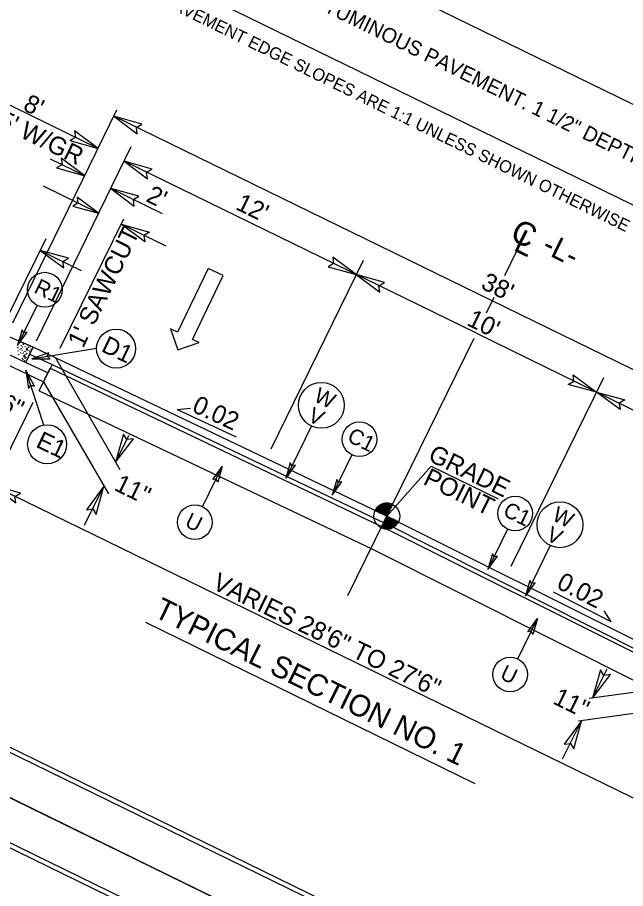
# Model space of a CAD drawing. Extents: x 1518247 to 1523638, y 635234 to 639927.
# Drawn here: x 1521566.4 to 1521902.2, y 638576.7 to 639057.9 of the extents above; entities that cross this region are included whole.
import ezdxf

# ---------------------------------------------------------------- set-up
doc = ezdxf.new("R2010")
doc.units = 0
for name, color, linetype in [('Default', 7, 'Continuous'), ('DTM TIN Hull White', 7, 'Continuous'), ('Old_Level_21', 7, 'Continuous'), ('Prop Dimension', 7, 'Continuous'), ('Prop Dimension Text', 7, 'Continuous'), ('Prop Lane Arrow CELL', 7, 'Continuous'), ('Prop Shade Light', 7, 'Continuous'), ('Sheet Cutting Line CELL', 7, 'Continuous'), ('Sheet Plot Border Inside CELL', 7, 'Continuous'), ('Sheet Plot Border Outside CELL', 7, 'Continuous'), ('Sheet Typical CELL', 7, 'Continuous'), ('Typical Curb CELL', 7, 'Continuous'), ('Typical Grade Point Symbol CELL', 7, 'Continuous'), ('Typical ID Circle CELL', 7, 'Continuous'), ('Typical Pavement Slope CELL', 7, 'Continuous'), ('Typical Pavement Slope Information CELL', 7, 'Continuous'), ('Typical Text Centerline CELL', 7, 'Continuous'), ('Typical Text Grade Point CELL', 7, 'Continuous'), ('Typical Text ID Circle CELL', 7, 'Continuous'), ('Typical Text Label CELL', 7, 'Continuous')]:
    doc.layers.add(name, color=color, linetype=linetype)

# ---------------------------------------------------------------- blocks, each defined once
blk = doc.blocks.new('TERMINATOR')
at = {"layer": 'Prop Shade Light'}
blk.add_lwpolyline([(-0.469, 0.081), (0, 0), (-0.471, -0.083), (-0.411, 0)], close=True, dxfattribs=at)

msp = doc.modelspace()

# ---------------------------------------------------------------- linework, layer by layer
at = {"layer": 'Default'}
for points in [[(1522438.02, 638198.63), (1520925.25, 638938.49), (1521408.53, 639926.64), (1522921.3, 639186.78)], [(1520441.97, 637950.34), (1521954.73, 637210.48), (1522438.02, 638198.63), (1520925.25, 638938.49)]]:
    msp.add_lwpolyline(points, close=True, dxfattribs=at)
at = {"layer": 'DTM TIN Hull White'}
for p, q in [((1521578.45, 638851.68), (1521584.56, 638864.18)), ((1521584.56, 638864.18), (1521767.55, 638776.75)), ((1521578.45, 638851.68), (1521762.16, 638764.31)), ((1521949.57, 638685.65), (1521767.55, 638776.75)), ((1521943.46, 638673.16), (1521761.27, 638764.74))]:
    msp.add_line(p, q, dxfattribs=at)
at = {"layer": 'Prop Dimension'}
for p, q in [((1521610.99, 638985.59), (1521539.35, 639020.56)), ((1521563.96, 638889.26), (1521621.37, 639006.86)), ((1522037.58, 638799.28), (1521619.64, 639003.32)), ((1521576.87, 638879.35), (1521629.21, 638986.56)), ((1521603.63, 638970.46), (1521584.63, 638979.74)), ((1521819.91, 638883.5), (1521625.28, 638978.51)), ((1521611.26, 638949.8), (1521580.79, 638964.67)), ((1521646.5, 638949.53), (1521617.96, 638963.47)), ((1521589.97, 638875.29), (1521625.26, 638946.72)), ((1521648.52, 638931.58), (1521623.76, 638943.67)), ((1521560.46, 638891.25), (1521582.21, 638935.81)), ((1521579.02, 638929.27), (1521601.58, 638918.22)), ((1521706.53, 638819.6), (1521757.45, 638923.89)), ((1521819.91, 638883.5), (1522014.4, 638788.21)), ((1521587.36, 638869.93), (1521622.98, 638808.23)), ((1521839.12, 638754.75), (1521890.18, 638858.97)), ((1521580.88, 638856.62), (1521616.63, 638794.7)), ((1521549.01, 638792.36), (1521575.18, 638845.34)), ((1521620.66, 638812.25), (1521628.06, 638827.23)), ((1521794.86, 638810.04), (1521770.4, 638782.47)), ((1521918.24, 638620.97), (1521552.58, 638799.48)), ((1521603.45, 638777.4), (1521614.13, 638799.03)), ((1521884.07, 638681.96), (1521892.01, 638698.04)), ((1521952.32, 638691.4), (1521882.21, 638681.7)), ((1521946.26, 638678.93), (1521876.19, 638669.24)), ((1521867.46, 638648.34), (1521877.9, 638669.47))]:
    msp.add_line(p, q, dxfattribs=at)
at = {"layer": 'Prop Lane Arrow CELL'}
for p, q in [((1521671.77, 638919.3), (1521654.8, 638884.11)), ((1521680.07, 638915.3), (1521671.77, 638919.3)), ((1521663.09, 638880.11), (1521680.07, 638915.3)), ((1521654.8, 638884.11), (1521651.02, 638885.93)), ((1521651.02, 638885.93), (1521655, 638874.25)), ((1521655, 638874.25), (1521666.86, 638878.29)), ((1521666.86, 638878.29), (1521663.09, 638880.11))]:
    msp.add_line(p, q, dxfattribs=at)
at = {"layer": 'Prop Shade Light'}
for points in [[(1521568.97, 638885.32), (1521566.45, 638876.67), (1521571.78, 638884), (1521569.87, 638883.68)], [(1521583.84, 638872.72), (1521574.29, 638869.34), (1521584.48, 638869.28), (1521582.92, 638870.82)], [(1521575.86, 638854.19), (1521571.05, 638863.11), (1521572.57, 638853.02), (1521573.84, 638854.8)], [(1521674.27, 638802.64), (1521679.55, 638809.94), (1521677.04, 638801.23), (1521676.12, 638802.94)], [(1521717.1, 638811.92), (1521714.58, 638803.28), (1521719.92, 638810.6), (1521718, 638810.28)], [(1521742.73, 638802.74), (1521740.21, 638794.09), (1521745.54, 638801.42), (1521743.62, 638801.1)], [(1521828.73, 638761.71), (1521826.21, 638753.06), (1521831.55, 638760.39), (1521829.63, 638760.06)], [(1521849.42, 638746.92), (1521846.9, 638738.27), (1521852.23, 638745.6), (1521850.32, 638745.27)], [(1521848.32, 638718.56), (1521853.6, 638725.86), (1521851.08, 638717.15), (1521850.17, 638718.86)]]:
    msp.add_lwpolyline(points, close=True, dxfattribs=at)
at = {"layer": 'Sheet Cutting Line CELL'}
for p, q in [((1520925.25, 638938.49), (1522438.02, 638198.63)), ((1522438.02, 638198.63), (1520925.25, 638938.49))]:
    msp.add_line(p, q, dxfattribs=at)
at = {"layer": 'Sheet Plot Border Inside CELL'}
for points in [[(1522907.39, 639168.59), (1521410.35, 639900.76), (1520946.79, 638952.95), (1522443.84, 638220.77)], [(1522424.11, 638180.44), (1520927.06, 638912.61), (1520463.51, 637964.8), (1521960.55, 637232.62)]]:
    msp.add_lwpolyline(points, close=True, dxfattribs=at)
at = {"layer": 'Sheet Plot Border Outside CELL'}
for points in [[(1522921.3, 639186.78), (1521408.53, 639926.64), (1520925.25, 638938.49), (1522438.02, 638198.63)], [(1522438.02, 638198.63), (1520925.25, 638938.49), (1520441.97, 637950.34), (1521954.73, 637210.48)]]:
    msp.add_lwpolyline(points, close=True, dxfattribs=at)
at = {"layer": 'Sheet Typical CELL'}
for p, q in [((1521639.08, 639140.63), (1522147.89, 638891.78)), ((1521617.12, 639095.71), (1522125.92, 638846.87))]:
    msp.add_line(p, q, dxfattribs=at)
for points in [[(1522895.04, 639171.79), (1521547.57, 639830.81), (1521086.25, 638887.58), (1522433.73, 638228.56)], [(1522411.76, 638183.64), (1521064.29, 638842.66), (1520602.97, 637899.43), (1521950.45, 637240.41)]]:
    msp.add_lwpolyline(points, close=True, dxfattribs=at)
at = {"layer": 'Typical Curb CELL'}
for p, q in [((1521575.12, 638875.77), (1521562.32, 638881.37)), ((1521552.95, 638875.79), (1521571.04, 638867.41)), ((1521571.04, 638867.41), (1521575.12, 638875.77)), ((1521571.85, 638875.38), (1521571.21, 638874.68)), ((1521571.21, 638874.68), (1521572.05, 638874.22)), ((1521572.05, 638874.22), (1521571.85, 638875.38)), ((1521570.42, 638871.5), (1521569.77, 638870.81)), ((1521569.77, 638870.81), (1521570.62, 638870.34)), ((1521570.62, 638870.34), (1521570.42, 638871.5))]:
    msp.add_line(p, q, dxfattribs=at)
for centre in [(1521566.8, 638878.51), (1521567.83, 638878.45), (1521569.72, 638877.34), (1521569.77, 638877.76), (1521566.68, 638875.47), (1521566.86, 638873.66), (1521567.73, 638874.41), (1521568.19, 638872.66), (1521568.52, 638876.65), (1521568.54, 638875.02), (1521569.06, 638874.01), (1521569.25, 638872.23), (1521569.32, 638876.01), (1521569.81, 638872.86), (1521570.61, 638873.46), (1521570.69, 638876.1), (1521571.25, 638876.73), (1521571.52, 638872.41), (1521572.5, 638875.77), (1521572.53, 638876.66), (1521572.7, 638873.9), (1521573.23, 638873.24), (1521573.5, 638876.04), (1521573.84, 638874.77), (1521574.14, 638874.06), (1521574.36, 638874.82), (1521567.06, 638871.79), (1521569.18, 638869.58), (1521569.62, 638868.92), (1521570.42, 638868.28), (1521570.81, 638869.61), (1521571.07, 638871.9), (1521571.27, 638870.03), (1521572.4, 638870.89), (1521573.1, 638871.83)]:
    msp.add_circle(centre, 0.064, dxfattribs=at)
at = {"layer": 'Typical Grade Point Symbol CELL'}
for p, q in [((1521764, 638785.62), (1521770.4, 638782.47)), ((1521770.4, 638782.47), (1521764, 638785.62)), ((1521773.54, 638788.88), (1521770.4, 638782.47)), ((1521767.26, 638776.06), (1521770.4, 638782.47)), ((1521770.4, 638782.47), (1521776.81, 638779.33))]:
    msp.add_line(p, q, dxfattribs=at)
for points in [[(1521770.45, 638782.57), (1521764.04, 638785.71), (1521764.04, 638785.71)], [(1521770.51, 638782.7), (1521764.1, 638785.84)], [(1521770.58, 638782.82), (1521764.18, 638785.96)], [(1521770.64, 638782.95), (1521764.24, 638786.09)], [(1521770.7, 638783.08), (1521764.32, 638786.21)], [(1521770.77, 638783.21), (1521764.4, 638786.33)], [(1521770.83, 638783.34), (1521764.48, 638786.45)], [(1521770.89, 638783.47), (1521764.57, 638786.56)], [(1521770.95, 638783.59), (1521764.64, 638786.69)], [(1521771.02, 638783.72), (1521764.73, 638786.8)], [(1521771.08, 638783.85), (1521764.83, 638786.91)], [(1521771.14, 638783.98), (1521764.92, 638787.03)], [(1521771.21, 638784.11), (1521765.01, 638787.14)], [(1521771.27, 638784.23), (1521765.11, 638787.25)], [(1521771.33, 638784.36), (1521765.21, 638787.36)], [(1521771.39, 638784.49), (1521765.31, 638787.47)], [(1521771.46, 638784.62), (1521765.42, 638787.58)], [(1521771.52, 638784.75), (1521765.52, 638787.69)], [(1521771.58, 638784.88), (1521765.64, 638787.79)], [(1521771.65, 638785), (1521765.76, 638787.89)], [(1521771.71, 638785.13), (1521765.88, 638787.99)], [(1521771.77, 638785.26), (1521766, 638788.09)], [(1521771.83, 638785.39), (1521766.12, 638788.19)], [(1521771.9, 638785.52), (1521766.26, 638788.28)], [(1521771.96, 638785.64), (1521766.39, 638788.37)], [(1521772.02, 638785.77), (1521766.52, 638788.47)], [(1521772.09, 638785.9), (1521766.67, 638788.55)], [(1521772.15, 638786.03), (1521766.82, 638788.64)], [(1521772.21, 638786.16), (1521766.97, 638788.73)], [(1521772.27, 638786.29), (1521767.12, 638788.81)], [(1521772.34, 638786.41), (1521767.28, 638788.89)], [(1521772.4, 638786.54), (1521767.44, 638788.97)], [(1521772.46, 638786.67), (1521767.62, 638789.04)], [(1521772.53, 638786.8), (1521767.8, 638789.12)], [(1521772.59, 638786.93), (1521767.97, 638789.19)], [(1521772.65, 638787.05), (1521768.16, 638789.25)], [(1521772.71, 638787.18), (1521768.37, 638789.31)], [(1521772.78, 638787.31), (1521768.57, 638789.37)], [(1521772.84, 638787.44), (1521768.79, 638789.42)], [(1521772.9, 638787.57), (1521769.01, 638789.47)], [(1521772.96, 638787.7), (1521769.25, 638789.52)], [(1521773.03, 638787.82), (1521769.5, 638789.55)], [(1521773.09, 638787.95), (1521769.76, 638789.59)], [(1521773.15, 638788.08), (1521770.05, 638789.6)], [(1521773.22, 638788.21), (1521770.35, 638789.61)], [(1521773.28, 638788.34), (1521770.69, 638789.61)], [(1521773.34, 638788.47), (1521771.05, 638789.59)], [(1521773.4, 638788.59), (1521771.5, 638789.53)], [(1521773.47, 638788.72), (1521772.01, 638789.43)], [(1521773.53, 638788.85), (1521772.83, 638789.19)], [(1521775.73, 638777.72), (1521769.56, 638780.74)], [(1521775.83, 638777.83), (1521769.62, 638780.87)], [(1521775.92, 638777.94), (1521769.68, 638781)], [(1521776.02, 638778.06), (1521769.75, 638781.13)], [(1521776.11, 638778.17), (1521769.81, 638781.26)], [(1521776.2, 638778.29), (1521769.87, 638781.38)], [(1521776.28, 638778.41), (1521769.94, 638781.51)], [(1521776.35, 638778.53), (1521770, 638781.64)], [(1521776.43, 638778.65), (1521770.06, 638781.77)], [(1521776.51, 638778.77), (1521770.12, 638781.9)], [(1521776.58, 638778.89), (1521770.19, 638782.03)], [(1521776.65, 638779.02), (1521770.25, 638782.15)], [(1521776.72, 638779.14), (1521770.31, 638782.28)], [(1521776.79, 638779.27), (1521776.79, 638779.27), (1521770.38, 638782.41)], [(1521768.21, 638775.68), (1521767.3, 638776.13)], [(1521768.93, 638775.49), (1521767.36, 638776.26)], [(1521769.43, 638775.4), (1521767.42, 638776.38)], [(1521769.85, 638775.35), (1521767.49, 638776.51)], [(1521770.21, 638775.34), (1521767.55, 638776.64)], [(1521770.55, 638775.33), (1521767.61, 638776.77)], [(1521770.84, 638775.35), (1521767.67, 638776.9)], [(1521771.11, 638775.37), (1521767.74, 638777.03)], [(1521771.37, 638775.4), (1521767.8, 638777.15)], [(1521771.62, 638775.44), (1521767.86, 638777.28)], [(1521771.86, 638775.48), (1521767.92, 638777.41)], [(1521772.08, 638775.53), (1521767.99, 638777.54)], [(1521772.3, 638775.59), (1521768.05, 638777.67)], [(1521772.5, 638775.64), (1521768.11, 638777.79)], [(1521772.69, 638775.71), (1521768.18, 638777.92)], [(1521772.88, 638775.78), (1521768.24, 638778.05)], [(1521773.06, 638775.85), (1521768.3, 638778.18)], [(1521773.24, 638775.92), (1521768.36, 638778.31)], [(1521773.41, 638775.99), (1521768.43, 638778.44)], [(1521773.58, 638776.07), (1521768.49, 638778.56)], [(1521773.73, 638776.16), (1521768.55, 638778.69)], [(1521773.89, 638776.24), (1521768.62, 638778.82)], [(1521774.04, 638776.32), (1521768.68, 638778.95)], [(1521774.18, 638776.41), (1521768.74, 638779.08)], [(1521774.32, 638776.5), (1521768.8, 638779.21)], [(1521774.45, 638776.6), (1521768.87, 638779.33)], [(1521774.59, 638776.69), (1521768.93, 638779.46)], [(1521774.72, 638776.78), (1521768.99, 638779.59)], [(1521774.84, 638776.88), (1521769.06, 638779.72)], [(1521774.96, 638776.98), (1521769.12, 638779.85)], [(1521775.08, 638777.08), (1521769.18, 638779.97)], [(1521775.2, 638777.18), (1521769.24, 638780.1)], [(1521775.32, 638777.28), (1521769.31, 638780.23)], [(1521775.43, 638777.39), (1521769.37, 638780.36)], [(1521775.53, 638777.5), (1521769.43, 638780.49)], [(1521775.64, 638777.61), (1521769.5, 638780.62)]]:
    msp.add_lwpolyline(points, dxfattribs=at)
msp.add_circle((1521770.41, 638782.47), 7.14, dxfattribs=at)
for start, end in [(63.8867, 153.8867), (243.8867, 333.8867)]:
    msp.add_arc((1521770.41, 638782.47), 7.14, start, end, dxfattribs=at)
at = {"layer": 'Typical ID Circle CELL'}
for p, q in [((1521577.32, 638898.94), (1521566.45, 638876.67)), ((1521574.29, 638869.34), (1521610.13, 638875.2)), ((1521580.99, 638832.76), (1521571.06, 638863.11)), ((1521728.74, 638832.28), (1521714.58, 638803.28)), ((1521751.08, 638816.36), (1521740.21, 638794.09)), ((1521668.64, 638787.69), (1521679.55, 638809.94)), ((1521837.08, 638775.33), (1521826.21, 638753.06)), ((1521860.57, 638766.26), (1521846.9, 638738.27)), ((1521842.69, 638703.61), (1521853.6, 638725.86))]:
    msp.add_line(p, q, dxfattribs=at)
for centre, radius in [((1521581.52, 638907.55), 9.59), ((1521620.91, 638874.99), 10.78), ((1521734.28, 638843.67), 12.66), ((1521755.28, 638824.97), 9.59), ((1521582.83, 638822.14), 10.78), ((1521841.29, 638783.94), 9.59), ((1521866.02, 638777.69), 12.66), ((1521664.43, 638779.09), 9.59), ((1521838.48, 638695), 9.59)]:
    msp.add_circle(centre, radius, dxfattribs=at)
at = {"layer": 'Typical Pavement Slope CELL'}
for p, q in [((1521541.69, 638875.33), (1521580.87, 638856.63)), ((1521770.4, 638782.47), (1521575.12, 638875.77)), ((1521571.04, 638867.41), (1521583.32, 638861.54)), ((1521573.24, 638872.01), (1521585.52, 638866.14)), ((1521585.52, 638866.14), (1521580.87, 638856.63)), ((1521585.52, 638866.14), (1521768.87, 638778.78)), ((1521770.4, 638782.47), (1521964.09, 638685.53)), ((1521950.42, 638687.37), (1521768.58, 638778.92))]:
    msp.add_line(p, q, dxfattribs=at)
at = {"layer": 'Typical Pavement Slope Information CELL'}
for p, q in [((1521654.64, 638841.45), (1521661.91, 638842.1)), ((1521654.64, 638841.45), (1521687.3, 638826.31)), ((1521894.28, 638724.08), (1521862.38, 638740.52)), ((1521894.28, 638724.08), (1521890.33, 638730.22))]:
    msp.add_line(p, q, dxfattribs=at)
at = {"layer": 'Typical Text Centerline CELL'}
for p, q in [((1521835.53, 638915.39), (1521842.4, 638929.41)), ((1521825.46, 638894.83), (1521829.64, 638903.37)), ((1521748.91, 638738.61), (1521818.55, 638880.73))]:
    msp.add_line(p, q, dxfattribs=at)
at = {"layer": 'Typical Text Grade Point CELL'}
msp.add_line((1521794.86, 638810.04), (1521831.81, 638791.93), dxfattribs=at)
at = {"layer": 'Typical Text Label CELL'}
msp.add_line((1521637.17, 638723.86), (1521819.07, 638634.73), dxfattribs=at)

# ---------------------------------------------------------------- block references
at = {"layer": 'Prop Dimension'}
for p, xscale, yscale, rotation in [((1521619.64, 639003.32), 33.82820784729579, -36.41552511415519, 153.97926941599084), ((1521610.99, 638985.59), 33.82820784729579, -36.41552511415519, -26.020730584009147), ((1521603.63, 638970.46), 33.82820784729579, -36.41552511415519, -26.020730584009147), ((1521625.28, 638978.51), 33.82820784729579, -36.41552511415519, 153.97926941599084), ((1521617.96, 638963.47), 33.82820784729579, -36.41552511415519, 153.97926941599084), ((1521611.26, 638949.8), 30.938856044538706, -33.30518407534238, -25.836011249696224), ((1521623.76, 638943.67), 33.82820784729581, 36.4155251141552, 153.89617982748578), ((1521579.02, 638929.27), 33.82820784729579, -36.41552511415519, 153.97926941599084), ((1521753.52, 638915.85), 33.82820784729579, -36.41552511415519, -26.020730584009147), ((1521753.52, 638915.85), 33.82820784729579, -36.41552511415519, 153.97926941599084), ((1521886.24, 638850.94), 33.82820784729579, 36.41552511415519, -26.103820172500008), ((1521886.24, 638850.94), 33.82820784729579, 36.41552511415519, 153.8961798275), ((1521620.67, 638812.25), 33.82820784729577, -36.41552511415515, -116.32645047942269), ((1521552.58, 638799.48), 33.82820784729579, -36.41552511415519, 153.97926941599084), ((1521614.14, 638799.02), 33.82820784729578, -36.41552511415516, 64.28897779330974), ((1521884.07, 638681.96), 33.82820784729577, -36.41552511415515, -116.32645047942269), ((1521877.9, 638669.47), 33.82820784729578, -36.41552511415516, 64.28897779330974)]:
    msp.add_blockref('TERMINATOR', p, dxfattribs=dict(at, xscale=xscale, yscale=yscale, rotation=rotation))

# ---------------------------------------------------------------- texts
at = {"layer": 'Old_Level_21'}
msp.add_text('NOTE:  PAVEMENT EDGE SLOPES ARE 1:1 UNLESS SHOWN OTHERWISE', height=6.75, rotation=333.8298, dxfattribs=at).set_placement((1521617.01, 639079.5))
at = {"layer": 'Prop Dimension'}
for s, height, rotation, p in [("10.5' W/GR", 9.969, 333.8962, (1521538.29, 639006.22)), ("8'", 9.969, 333.9793, (1521568.94, 639007.04)), ("2'", 9.969, 333.9793, (1521636.85, 638956.62)), ("12'", 9.969, 333.9793, (1521686.35, 638952.24)), ("1' SAWCUT", 10, 63.9377, (1521602.64, 638874.82)), ("38'", 9.969, 333.9793, (1521821.74, 638908.51)), ("10'", 9.969, 333.9793, (1521814.01, 638888.19)), ('6"', 9.969, 333.9793, (1521555.92, 638841.71)), ('11"', 9.969, 333.9793, (1521619.28, 638797.08)), ('VARIES 28\'6" TO 27\'6"', 9.9687, 333.9793, (1521673.42, 638742.61)), ('11"', 9.969, 333.9793, (1521861.44, 638679.18))]:
    msp.add_text(s, height=height, rotation=rotation, dxfattribs=at).set_placement(p)
at = {"layer": 'Prop Dimension Text'}
for s, height, rotation, p in [('-L-', 11.962, 333.9793, (1521855.33, 638928.64)), ('TYPICAL SECTION NO. 1', 11.9625, 333.8962, (1521641.13, 638727.2))]:
    msp.add_text(s, height=height, rotation=rotation, dxfattribs=at).set_placement(p)
at = {"layer": 'Sheet Typical CELL'}
msp.add_text('MILLING BITUMINOUS PAVEMENT. 1 1/2" DEPTH', height=8.1788, rotation=333.8298, dxfattribs=at).set_placement((1521683.86, 639086.68))
at = {"layer": 'Typical Pavement Slope Information CELL'}
for rotation, p in [(335.125, (1521662.26, 638840.45)), (332.7504, (1521863.54, 638743.01))]:
    msp.add_text('0.02', height=9.969, rotation=rotation, dxfattribs=at).set_placement(p)
at = {"layer": 'Typical Text Centerline CELL'}
for s, height, rotation, p in [('C', 13.08, 333.8962, (1521837.75, 638935.48)), ('L', 13.09, 333.8431, (1521839.69, 638929.56))]:
    msp.add_text(s, height=height, rotation=rotation, dxfattribs=at).set_placement(p)
at = {"layer": 'Typical Text Grade Point CELL'}
for s, p in [('GRADE', (1521792.58, 638813.44)), ('POINT', (1521789.88, 638800.4))]:
    msp.add_text(s, height=9.969, rotation=333.8962, dxfattribs=at).set_placement(p)
at = {"layer": 'Typical Text ID Circle CELL'}
for s, height, rotation, p in [('R1', 8.581, 333.9793, (1521574.99, 638906.23)), ('D1', 9.65, 334.5375, (1521612.19, 638873.72)), ('W', 8.58, 333.9793, (1521729.51, 638846.23)), ('V', 8.58, 333.9793, (1521726.19, 638835.33)), ('E1', 9.65, 334.5375, (1521576.07, 638820.95)), ('C1', 8.581, 333.9793, (1521747.95, 638824.04)), ('C1', 8.581, 333.9793, (1521833.96, 638783.01)), ('W', 8.58, 333.9793, (1521861.11, 638780.42)), ('U', 8.58, 333.8962, (1521658.28, 638777.05)), ('V', 8.58, 333.9793, (1521857.8, 638769.53)), ('U', 8.58, 333.8962, (1521832.32, 638692.97))]:
    msp.add_text(s, height=height, rotation=rotation, dxfattribs=at).set_placement(p)

doc.saveas('drawing.dxf')
